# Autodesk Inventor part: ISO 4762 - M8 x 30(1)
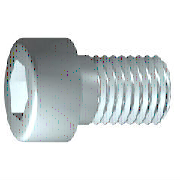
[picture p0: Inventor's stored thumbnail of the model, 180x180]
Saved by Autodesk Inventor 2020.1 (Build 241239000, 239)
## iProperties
Created: 2019-01
Part Number: ISO 4762 - M8 x 30(1)
Material: Edelstahl, 440C
Description: Innensechskantschraube
Document SubType Name: Modeling
Standard: ISO 4762
Designer: lutzd
Standard Revision: Fourth edition 2004-03-01
Standards Organization: ISO
Language: de-DE
Size Designation: M8 x 30
Categories: <MemberInstance><Categories><Category DisplayName="Verbindungselemente" InternalName="e4da775c-781d-43d5-af7c-5136215cf5a6" Mnemonic="FSTN"><Category DisplayNam
Mass: 18.6647 g
Surface Area: 14.1036 cm^2
Volume: 2.40835 cm^3
Density: 7.75 g/cm^3
Appearance: Halbpoliert
IsCustomPart: 0
Author: lutzd
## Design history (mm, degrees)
workplane "Work Plane1"
fillet "Fillet2" dims "d30" = 0.1 (= R)
sketch "Skizze1"
  geometry: L1 (-2, 0)-(30, 0); L2 (30, 0)-(30, 4); L3 (30, 4)-(3.125, 4); L4 (3.125, 4)-(2.358, 4); L5 (2.358, 4)-(0, 4); L6 (0, 4)-(0, 6.5); L7 (0, 6.5)-(-8, 6.5); L8 (-8, 6.5)-(-8, 3.464); L9 (-8, 3.464)-(-4, 3.464); L10 (-4, 3.464)-(-2, 0); L11 (-15.6, 0)-(37.6, 0) reference; L12 (0, -1.3)-(0, 7.8) reference; L13 (3.125, 4)-(0, 4)
  constraints: 22 end point, 6 parallel, 2 collinear, 2 perpendicular, 1 horizontal, 1 point on line
  dimensions: "d1" = 26.875 distance from line of L3.end L2 (= GEL); "d2" = 0.76691 distance of L4.end L3.end (computed from GAL); "d3" = 8 distance between parallel lines of L8 L6 (= KOH); "d4" = 4 distance of L8.end L9.end (= INTI); "d5" = 60 deg angle of L10 L1; "d6" = 8 diameter of L3 L1 (= GD); "d7" = 8 diameter of L5 L1 (= BDM); "d8" = 6.9282 diameter of L9 L1 (= 1.1547 x SW); "d9" = 13 diameter of L7 L1 (= KOD); "d26" = 30 distance between parallel lines of L12 L2 (= NLG)
revolve "Körper" sketch "Skizze1" stored, may be unused: angle "d10" = 90 deg
sketch "Skizze2"
  geometry: L1 (0, -9.1)-(0, 9.1) reference; L2 (-9.1, 0)-(9.1, 0) reference; L3 (3.464, 0)-(1.732, -3); L4 (1.732, -3)-(-1.732, -3); L5 (-1.732, -3)-(-3.464, 0); L6 (-3.464, 0)-(-1.732, 3); L7 (-1.732, 3)-(1.732, 3); L8 (1.732, 3)-(3.464, 0); 2 further points
  constraints: 12 end point, 1 coincident, 1 horizontal alignment, 1 point on line, 12 other
extrude "Loch" join sketch "Skizze2" stored distance "d11" = 10; taper "d12" = 0 deg
body "Solid1"
fillet "Rundung1" dims "d17" = 0.8 (= RR)
feature "Gewinde" dims "d13" = 26.875 (= GEL), "d14" = 0
chamfer "Fase1" distance "d15" = 0.76681 (= -0.5 x SPD + 0.5 x GD); stored, may be unused: second distance "d16" = 0.76681 (= GUL), angle "d27" = 45 deg
other parameters: "GD" = 8 [user parameter; used in 2 equation terms], "NLG" = 30 [user parameter; used in 1 equation term], "GEL" = 26.875 [user parameter; used in 2 equation terms], "KOD" = 13 [user parameter; used in 1 equation term], "KOH" = 8 [user parameter; used in 1 equation term], "INTI" = 4 [user parameter; used in 1 equation term], "GAL" = 0.76681 (= 0.61345 x PTC) [user parameter; used in 1 equation term], "GUL" = 0.76681 (= 0.61345 x PTC) [user parameter; used in 1 equation term], "BDM" = 8 (= NND) [user parameter; used in 1 equation term], "SW" = 6 [user parameter; used in 2 equation terms], "RR" = 0.8 [user parameter; used in 1 equation term], "SPD" = 6.46637 (= NND - 1.2269 x PTC) [user parameter; used in 1 equation term], "d19" = 0, "d28" = 0, "d29" = 0, "R" = 0.1 [user parameter; used in 1 equation term], "TOA" = 30 deg [user parameter], "GD1" = 6.46637 (= THREADDIA - 1.2269 x PTC) [user parameter], "THREADDIA" = 8 [user parameter; used in 1 equation term], "FAWI" = 45 deg [user parameter], "TPU" = 8 (computed from PTC) [user parameter], "PTC" = 1.25 [user parameter; used in 5 equation terms], "NND" = 8 [user parameter; used in 2 equation terms], "E0" = 6.93 (= 1.155 x SW) [user parameter]
